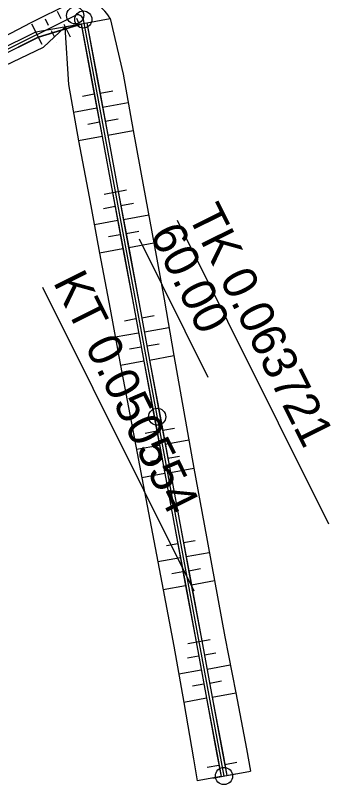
# Model space of a CAD drawing. Extents: x -481685 to -479315, y -1112639 to -1112242.
# Drawn here: x -481631.4 to -481603.8, y -1112628.4 to -1112561.1 of the extents above; entities that cross this region are included whole.
import ezdxf

# ---------------------------------------------------------------- set-up
doc = ezdxf.new("R2010")
doc.units = 0
for name, color, linetype in [('CP14_HATCH_SLOPE_L', 7, 'Continuous'), ('CP14_HATCH_SLOPE_R', 7, 'Continuous'), ('CP14_HECTOMETRY', 7, 'Continuous'), ('CP14_HLBODY', 7, 'Continuous'), ('CP14_HRANA_TELESO', 7, 'Continuous'), ('CP14_KORUNA', 7, 'Continuous'), ('CP14_OSA', 7, 'Continuous'), ('CP14_STANICENI', 7, 'Continuous'), ('CP14_VOZOVKA', 7, 'Continuous'), ('CP14_ZPEVKRAJ', 7, 'Continuous')]:
    doc.layers.add(name, color=color, linetype=linetype)

msp = doc.modelspace()

# ---------------------------------------------------------------- linework, layer by layer
at = {"layer": 'CP14_HATCH_SLOPE_L'}
for p, q in [((-481627.352, -1112561.377), (-481627.68, -1112560.719)), ((-481625.108, -1112561.723), (-481623.092, -1112561.348)), ((-481628.471, -1112561.935), (-481628.734, -1112561.407)), ((-481623.966, -1112567.868), (-481622.837, -1112567.658)), ((-481621.708, -1112567.448), (-481621.708, -1112567.448)), ((-481623.737, -1112569.096), (-481621.489, -1112568.678)), ((-481623.509, -1112570.325), (-481622.39, -1112570.117)), ((-481621.271, -1112569.909), (-481621.271, -1112569.909)), ((-481623.28, -1112571.554), (-481621.053, -1112571.14)), ((-481622.138, -1112577.699), (-481621.034, -1112577.494)), ((-481619.931, -1112577.289), (-481619.931, -1112577.289)), ((-481621.909, -1112578.928), (-481619.706, -1112578.518)), ((-481621.681, -1112580.157), (-481620.581, -1112579.952)), ((-481619.481, -1112579.748), (-481619.481, -1112579.748)), ((-481621.452, -1112581.386), (-481619.257, -1112580.978)), ((-481620.31, -1112587.531), (-481619.228, -1112587.33)), ((-481618.145, -1112587.128), (-481618.145, -1112587.128)), ((-481620.081, -1112588.759), (-481617.931, -1112588.36)), ((-481617.718, -1112589.591), (-481617.718, -1112589.591)), ((-481619.853, -1112589.988), (-481618.786, -1112589.79)), ((-481619.624, -1112591.217), (-481617.505, -1112590.823)), ((-481616.42, -1112596.979), (-481616.42, -1112596.979)), ((-481618.482, -1112597.362), (-481617.451, -1112597.17)), ((-481618.253, -1112598.591), (-481616.196, -1112598.208)), ((-481618.025, -1112599.82), (-481616.998, -1112599.629)), ((-481615.972, -1112599.438), (-481615.972, -1112599.438)), ((-481617.796, -1112601.049), (-481615.747, -1112600.668)), ((-481616.654, -1112607.194), (-481615.641, -1112607.006)), ((-481614.628, -1112606.817), (-481614.628, -1112606.817)), ((-481616.425, -1112608.422), (-481614.404, -1112608.047)), ((-481616.197, -1112609.651), (-481615.188, -1112609.464)), ((-481614.18, -1112609.276), (-481614.18, -1112609.276)), ((-481615.968, -1112610.88), (-481613.955, -1112610.506)), ((-481614.826, -1112617.025), (-481613.82, -1112616.838)), ((-481612.814, -1112616.651), (-481612.814, -1112616.651)), ((-481614.597, -1112618.254), (-481612.568, -1112617.877)), ((-481612.323, -1112619.103), (-481612.323, -1112619.103)), ((-481614.369, -1112619.483), (-481613.346, -1112619.293)), ((-481614.14, -1112620.712), (-481612.077, -1112620.328)), ((-481613.046, -1112626.596), (-481612.008, -1112626.403)), ((-481610.969, -1112626.21), (-481610.969, -1112626.21)), ((-481612.866, -1112627.564), (-481610.8, -1112627.18))]:
    msp.add_line(p, q, dxfattribs=at)
at = {"layer": 'CP14_HATCH_SLOPE_R'}
for p, q in [((-481626.015, -1112561.292), (-481625.75, -1112561.91)), ((-481627.12, -1112561.843), (-481626.573, -1112562.941)), ((-481625.62, -1112561.818), (-481627.058, -1112562.085)), ((-481628.239, -1112562.4), (-481627.992, -1112562.896)), ((-481625.486, -1112562.529), (-481625.486, -1112562.529)), ((-481627.745, -1112563.392), (-481627.745, -1112563.392)), ((-481624.477, -1112567.963), (-481625.492, -1112568.152)), ((-481626.508, -1112568.34), (-481626.508, -1112568.34)), ((-481624.249, -1112569.192), (-481626.288, -1112569.571)), ((-481626.067, -1112570.801), (-481626.067, -1112570.801)), ((-481624.02, -1112570.42), (-481625.044, -1112570.61)), ((-481623.792, -1112571.649), (-481625.847, -1112572.032)), ((-481624.694, -1112578.174), (-481624.694, -1112578.174)), ((-481622.649, -1112577.794), (-481623.672, -1112577.984)), ((-481622.421, -1112579.023), (-481624.463, -1112579.403)), ((-481624.233, -1112580.631), (-481624.233, -1112580.631)), ((-481622.192, -1112580.252), (-481623.212, -1112580.442)), ((-481621.963, -1112581.481), (-481624.002, -1112581.86)), ((-481620.821, -1112587.626), (-481621.837, -1112587.814)), ((-481622.853, -1112588.003), (-481622.853, -1112588.003)), ((-481620.592, -1112588.855), (-481622.626, -1112589.233)), ((-481620.364, -1112590.083), (-481621.382, -1112590.272)), ((-481622.399, -1112590.462), (-481622.399, -1112590.462)), ((-481620.135, -1112591.312), (-481622.172, -1112591.691)), ((-481618.993, -1112597.457), (-481620.002, -1112597.644)), ((-481621.01, -1112597.832), (-481621.01, -1112597.832)), ((-481618.764, -1112598.686), (-481620.776, -1112599.06)), ((-481620.542, -1112600.288), (-481620.542, -1112600.288)), ((-481618.536, -1112599.915), (-481619.539, -1112600.102)), ((-481618.307, -1112601.144), (-481620.308, -1112601.516)), ((-481619.143, -1112607.656), (-481619.143, -1112607.656)), ((-481617.165, -1112607.289), (-481618.154, -1112607.472)), ((-481616.936, -1112608.518), (-481618.911, -1112608.885)), ((-481616.708, -1112609.746), (-481617.693, -1112609.93)), ((-481618.678, -1112610.113), (-481618.678, -1112610.113)), ((-481616.479, -1112610.975), (-481618.445, -1112611.341)), ((-481615.337, -1112617.12), (-481616.316, -1112617.302)), ((-481617.296, -1112617.484), (-481617.296, -1112617.484)), ((-481615.108, -1112618.349), (-481617.077, -1112618.715)), ((-481614.88, -1112619.578), (-481615.87, -1112619.762)), ((-481616.859, -1112619.946), (-481616.859, -1112619.946)), ((-481614.651, -1112620.807), (-481616.64, -1112621.177)), ((-481615.625, -1112627.075), (-481615.625, -1112627.075)), ((-481613.557, -1112626.691), (-481614.591, -1112626.883)), ((-481613.377, -1112627.659), (-481615.458, -1112628.046))]:
    msp.add_line(p, q, dxfattribs=at)
msp.add_arc((-481625.549, -1112562.539), 2.731, 25.86811, 111.83802, dxfattribs=at)
at = {"layer": 'CP14_HECTOMETRY'}
msp.add_circle((-481618.966, -1112596.181), 0.75, dxfattribs=at)
at = {"layer": 'CP14_HLBODY'}
for p, q in [((-481617.224, -1112578.967), (-481603.979, -1112605.55)), ((-481629.008, -1112584.838), (-481615.763, -1112611.421))]:
    msp.add_line(p, q, dxfattribs=at)
for centre in [(-481626.143, -1112561.066), (-481625.429, -1112561.422), (-481613.12, -1112627.62)]:
    msp.add_circle(centre, 0.75, dxfattribs=at)
at = {"layer": 'CP14_HRANA_TELESO'}
for p, q in [((-481629.986, -1112561.696), (-481626.565, -1112560.004)), ((-481623.092, -1112561.348), (-481621.926, -1112566.217)), ((-481634.434, -1112563.982), (-481629.986, -1112561.696)), ((-481628.916, -1112563.844), (-481627.058, -1112562.085)), ((-481627.058, -1112562.085), (-481626.729, -1112567.11)), ((-481633.423, -1112566.01), (-481628.916, -1112563.844)), ((-481621.926, -1112566.217), (-481621.053, -1112571.14)), ((-481626.729, -1112567.11), (-481625.847, -1112572.032)), ((-481621.053, -1112571.14), (-481620.155, -1112576.059)), ((-481625.847, -1112572.032), (-481624.925, -1112576.946)), ((-481620.155, -1112576.059), (-481619.257, -1112580.978)), ((-481624.925, -1112576.946), (-481624.002, -1112581.86)), ((-481619.257, -1112580.978), (-481618.358, -1112585.896)), ((-481624.002, -1112581.86), (-481623.08, -1112586.774)), ((-481618.358, -1112585.896), (-481617.505, -1112590.823)), ((-481623.08, -1112586.774), (-481622.172, -1112591.691)), ((-481617.505, -1112590.823), (-481616.644, -1112595.749)), ((-481622.172, -1112591.691), (-481621.244, -1112596.604)), ((-481616.644, -1112595.749), (-481615.747, -1112600.668)), ((-481621.244, -1112596.604), (-481620.308, -1112601.516)), ((-481615.747, -1112600.668), (-481614.852, -1112605.587)), ((-481620.308, -1112601.516), (-481619.376, -1112606.428)), ((-481614.852, -1112605.587), (-481613.955, -1112610.506)), ((-481619.376, -1112606.428), (-481618.445, -1112611.341)), ((-481613.955, -1112610.506), (-481613.059, -1112615.425)), ((-481618.445, -1112611.341), (-481617.515, -1112616.254)), ((-481613.059, -1112615.425), (-481612.077, -1112620.328)), ((-481617.515, -1112616.254), (-481616.64, -1112621.177)), ((-481612.077, -1112620.328), (-481611.138, -1112625.239)), ((-481616.64, -1112621.177), (-481615.792, -1112626.105)), ((-481611.138, -1112625.239), (-481610.8, -1112627.18)), ((-481615.792, -1112626.105), (-481615.458, -1112628.046))]:
    msp.add_line(p, q, dxfattribs=at)
at = {"layer": 'CP14_KORUNA'}
for p, q in [((-481629.59, -1112562.492), (-481625.108, -1112561.723)), ((-481629.358, -1112562.958), (-481625.62, -1112561.818)), ((-481625.62, -1112561.818), (-481624.706, -1112566.734)), ((-481625.108, -1112561.723), (-481624.194, -1112566.639)), ((-481634.065, -1112564.722), (-481629.59, -1112562.492)), ((-481633.833, -1112565.188), (-481629.358, -1112562.958)), ((-481624.706, -1112566.734), (-481623.792, -1112571.649)), ((-481624.194, -1112566.639), (-481623.28, -1112571.554)), ((-481623.792, -1112571.649), (-481622.878, -1112576.565)), ((-481623.28, -1112571.554), (-481622.366, -1112576.47)), ((-481622.878, -1112576.565), (-481621.963, -1112581.481)), ((-481622.366, -1112576.47), (-481621.452, -1112581.386)), ((-481621.963, -1112581.481), (-481621.049, -1112586.397)), ((-481621.452, -1112581.386), (-481620.538, -1112586.302)), ((-481621.049, -1112586.397), (-481620.135, -1112591.312)), ((-481620.538, -1112586.302), (-481619.624, -1112591.217)), ((-481620.135, -1112591.312), (-481619.221, -1112596.228)), ((-481619.624, -1112591.217), (-481618.71, -1112596.133)), ((-481619.221, -1112596.228), (-481618.307, -1112601.144)), ((-481618.71, -1112596.133), (-481617.796, -1112601.049)), ((-481617.796, -1112601.049), (-481616.882, -1112605.965)), ((-481618.307, -1112601.144), (-481617.393, -1112606.06)), ((-481617.393, -1112606.06), (-481616.479, -1112610.975)), ((-481616.882, -1112605.965), (-481615.968, -1112610.88)), ((-481616.479, -1112610.975), (-481615.565, -1112615.891)), ((-481615.968, -1112610.88), (-481615.054, -1112615.796)), ((-481615.565, -1112615.891), (-481614.651, -1112620.807)), ((-481615.054, -1112615.796), (-481614.14, -1112620.712)), ((-481614.651, -1112620.807), (-481613.737, -1112625.723)), ((-481614.14, -1112620.712), (-481613.226, -1112625.628)), ((-481613.737, -1112625.723), (-481613.377, -1112627.659)), ((-481613.226, -1112625.628), (-481612.866, -1112627.564))]:
    msp.add_line(p, q, dxfattribs=at)
at = {"layer": 'CP14_OSA'}
for p, q in [((-481637.928, -1112566.937), (-481626.143, -1112561.066)), ((-481625.429, -1112561.422), (-481613.12, -1112627.62))]:
    msp.add_line(p, q, dxfattribs=at)
msp.add_arc((-481625.92, -1112561.513), 0.5, 10.53326, 116.48547, dxfattribs=at)
at = {"layer": 'CP14_STANICENI'}
for p, q in [((-481629.028, -1112563.62), (-481629.92, -1112561.83)), ((-481623.605, -1112576.7), (-481621.639, -1112576.335)), ((-481620.554, -1112580.626), (-481614.534, -1112592.709)), ((-481616.293, -1112616.026), (-481614.327, -1112615.661)), ((-481614.105, -1112627.795), (-481612.138, -1112627.429))]:
    msp.add_line(p, q, dxfattribs=at)
at = {"layer": 'CP14_VOZOVKA'}
for p, q in [((-481629.585, -1112562.501), (-481625.118, -1112561.725)), ((-481629.362, -1112562.949), (-481625.61, -1112561.816)), ((-481625.61, -1112561.816), (-481624.696, -1112566.732)), ((-481625.118, -1112561.725), (-481624.204, -1112566.64)), ((-481634.06, -1112564.731), (-481629.585, -1112562.501)), ((-481633.837, -1112565.179), (-481629.362, -1112562.949)), ((-481624.696, -1112566.732), (-481623.782, -1112571.648)), ((-481624.204, -1112566.64), (-481623.29, -1112571.556)), ((-481623.782, -1112571.648), (-481622.868, -1112576.563)), ((-481623.29, -1112571.556), (-481622.376, -1112576.472)), ((-481622.868, -1112576.563), (-481621.954, -1112581.479)), ((-481622.376, -1112576.472), (-481621.462, -1112581.388)), ((-481621.954, -1112581.479), (-481621.04, -1112586.395)), ((-481621.462, -1112581.388), (-481620.548, -1112586.303)), ((-481621.04, -1112586.395), (-481620.126, -1112591.311)), ((-481620.548, -1112586.303), (-481619.634, -1112591.219)), ((-481620.126, -1112591.311), (-481619.212, -1112596.226)), ((-481619.634, -1112591.219), (-481618.72, -1112596.135)), ((-481619.212, -1112596.226), (-481618.298, -1112601.142)), ((-481618.72, -1112596.135), (-481617.806, -1112601.051)), ((-481617.806, -1112601.051), (-481616.892, -1112605.966)), ((-481618.298, -1112601.142), (-481617.384, -1112606.058)), ((-481617.384, -1112606.058), (-481616.47, -1112610.974)), ((-481616.892, -1112605.966), (-481615.978, -1112610.882)), ((-481616.47, -1112610.974), (-481615.555, -1112615.889)), ((-481615.978, -1112610.882), (-481615.064, -1112615.798)), ((-481615.555, -1112615.889), (-481614.641, -1112620.805)), ((-481615.064, -1112615.798), (-481614.15, -1112620.714)), ((-481614.641, -1112620.805), (-481613.727, -1112625.721)), ((-481614.15, -1112620.714), (-481613.236, -1112625.629)), ((-481613.727, -1112625.721), (-481613.367, -1112627.658)), ((-481613.236, -1112625.629), (-481612.876, -1112627.566))]:
    msp.add_line(p, q, dxfattribs=at)
at = {"layer": 'CP14_ZPEVKRAJ'}
for p, q in [((-481629.585, -1112562.501), (-481625.118, -1112561.725)), ((-481629.362, -1112562.949), (-481625.61, -1112561.816)), ((-481625.61, -1112561.816), (-481624.696, -1112566.732)), ((-481625.118, -1112561.725), (-481624.204, -1112566.64)), ((-481634.06, -1112564.731), (-481629.585, -1112562.501)), ((-481633.837, -1112565.179), (-481629.362, -1112562.949)), ((-481624.696, -1112566.732), (-481623.782, -1112571.648)), ((-481624.204, -1112566.64), (-481623.29, -1112571.556)), ((-481623.782, -1112571.648), (-481622.868, -1112576.563)), ((-481623.29, -1112571.556), (-481622.376, -1112576.472)), ((-481622.868, -1112576.563), (-481621.954, -1112581.479)), ((-481622.376, -1112576.472), (-481621.462, -1112581.388)), ((-481621.954, -1112581.479), (-481621.04, -1112586.395)), ((-481621.462, -1112581.388), (-481620.548, -1112586.303)), ((-481621.04, -1112586.395), (-481620.126, -1112591.311)), ((-481620.548, -1112586.303), (-481619.634, -1112591.219)), ((-481620.126, -1112591.311), (-481619.212, -1112596.226)), ((-481619.634, -1112591.219), (-481618.72, -1112596.135)), ((-481619.212, -1112596.226), (-481618.298, -1112601.142)), ((-481618.72, -1112596.135), (-481617.806, -1112601.051)), ((-481617.806, -1112601.051), (-481616.892, -1112605.966)), ((-481618.298, -1112601.142), (-481617.384, -1112606.058)), ((-481617.384, -1112606.058), (-481616.47, -1112610.974)), ((-481616.892, -1112605.966), (-481615.978, -1112610.882)), ((-481616.47, -1112610.974), (-481615.555, -1112615.889)), ((-481615.978, -1112610.882), (-481615.064, -1112615.798)), ((-481615.555, -1112615.889), (-481614.641, -1112620.805)), ((-481615.064, -1112615.798), (-481614.15, -1112620.714)), ((-481614.641, -1112620.805), (-481613.727, -1112625.721)), ((-481614.15, -1112620.714), (-481613.236, -1112625.629)), ((-481613.727, -1112625.721), (-481613.367, -1112627.658)), ((-481613.236, -1112625.629), (-481612.876, -1112627.566))]:
    msp.add_line(p, q, dxfattribs=at)

# ---------------------------------------------------------------- texts
at = {"layer": 'CP14_HLBODY'}
for s, p in [('TK 0.063721', (-481616.329, -1112578.52)), ('KT 0.050554', (-481628.114, -1112584.392))]:
    msp.add_text(s, height=2.999, rotation=296.48548, dxfattribs=at).set_placement(p)
at = {"layer": 'CP14_STANICENI'}
msp.add_text('60.00', height=2.999, rotation=296.48548, dxfattribs=at).set_placement((-481619.66, -1112580.179))

doc.saveas('drawing.dxf')
